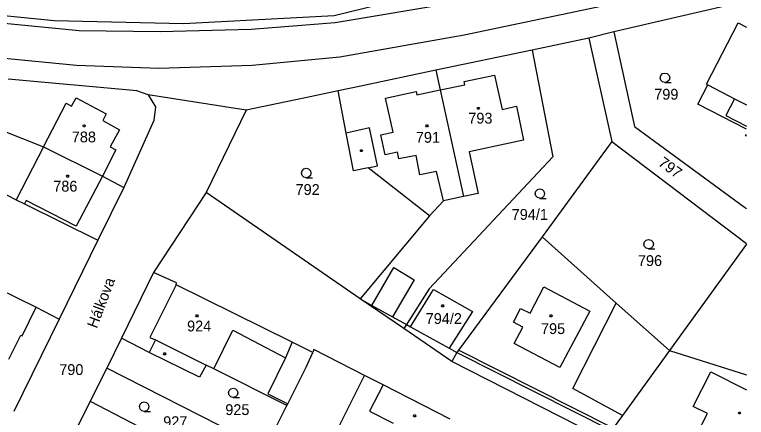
# Model space of a CAD drawing. Extents: x -621797 to -620972, y -1175539 to -1174697.
# Drawn here: x -621092 to -620977.2, y -1175193.8 to -1175130.5 of the extents above; entities that cross this region are included whole.
import ezdxf

# ---------------------------------------------------------------- set-up
doc = ezdxf.new("R2010")
doc.units = 0
for name, color, linetype in [('INZ mimo EON - nadz', 7, 'Continuous'), ('Rozvod plynu EON', 7, 'Continuous'), ('SDEL EON', 7, 'Continuous'), ('SDEL EON - popis', 7, 'Continuous'), ('Silnoproud EON', 7, 'Continuous'), ('Silnoproud EON - popis', 7, 'Continuous')]:
    doc.layers.add(name, color=color, linetype=linetype)

msp = doc.modelspace()

# ---------------------------------------------------------------- linework, layer by layer
at = {"layer": 'Rozvod plynu EON'}
for points in [[(-621019.15, -1175145.11), (-621019.06, -1175145.26), (-621019.15, -1175145.41), (-621019.33, -1175145.41), (-621019.42, -1175145.26), (-621019.33, -1175145.11)], [(-621081.02, -1175147.84), (-621080.93, -1175147.99), (-621081.02, -1175148.14), (-621081.2, -1175148.14), (-621081.29, -1175147.99), (-621081.2, -1175147.84)], [(-621027.19, -1175147.84), (-621027.1, -1175147.99), (-621027.19, -1175148.14), (-621027.37, -1175148.14), (-621027.46, -1175147.99), (-621027.37, -1175147.84)], [(-621037.49, -1175151.75), (-621037.4, -1175151.9), (-621037.49, -1175152.05), (-621037.67, -1175152.05), (-621037.76, -1175151.9), (-621037.67, -1175151.75)], [(-621083.61, -1175155.74), (-621083.52, -1175155.89), (-621083.61, -1175156.04), (-621083.79, -1175156.04), (-621083.88, -1175155.89), (-621083.79, -1175155.74)], [(-621024.75, -1175176.11), (-621024.66, -1175176.26), (-621024.75, -1175176.41), (-621024.93, -1175176.41), (-621025.02, -1175176.26), (-621024.93, -1175176.11)], [(-621063.3, -1175177.68), (-621063.21, -1175177.83), (-621063.3, -1175177.98), (-621063.48, -1175177.98), (-621063.57, -1175177.83), (-621063.48, -1175177.68)], [(-621007.71, -1175177.68), (-621007.62, -1175177.83), (-621007.71, -1175177.98), (-621007.89, -1175177.98), (-621007.98, -1175177.83), (-621007.89, -1175177.68)], [(-621068.39, -1175183.65), (-621068.3, -1175183.8), (-621068.39, -1175183.95), (-621068.57, -1175183.95), (-621068.66, -1175183.8), (-621068.57, -1175183.65)], [(-620978.14, -1175192.94), (-620978.05, -1175193.09), (-620978.14, -1175193.24), (-620978.32, -1175193.24), (-620978.41, -1175193.09), (-620978.32, -1175192.94)], [(-621029.15, -1175193.38), (-621029.06, -1175193.53), (-621029.15, -1175193.68), (-621029.33, -1175193.68), (-621029.42, -1175193.53), (-621029.33, -1175193.38)]]:
    msp.add_lwpolyline(points, close=True, dxfattribs=at)
at = {"layer": 'SDEL EON'}
for points in [[(-620989.92, -1175141.19), (-620990.3, -1175141.09), (-620990.57, -1175140.82), (-620990.67, -1175140.45), (-620990.57, -1175140.08), (-620990.3, -1175139.81), (-620989.93, -1175139.71), (-620989.56, -1175139.81), (-620989.29, -1175140.08), (-620989.19, -1175140.46), (-620989.29, -1175140.84), (-620989.56, -1175141.11), (-620989.94, -1175141.21), (-620988.94, -1175141.21)], [(-621046.23, -1175156.15), (-621046.61, -1175156.05), (-621046.88, -1175155.78), (-621046.98, -1175155.41), (-621046.88, -1175155.04), (-621046.61, -1175154.77), (-621046.24, -1175154.67), (-621045.87, -1175154.77), (-621045.6, -1175155.04), (-621045.5, -1175155.42), (-621045.6, -1175155.8), (-621045.87, -1175156.07), (-621046.25, -1175156.17), (-621045.25, -1175156.17)], [(-621009.55, -1175159.37), (-621009.93, -1175159.27), (-621010.2, -1175159), (-621010.3, -1175158.63), (-621010.2, -1175158.26), (-621009.93, -1175157.99), (-621009.56, -1175157.89), (-621009.19, -1175157.99), (-621008.92, -1175158.26), (-621008.82, -1175158.64), (-621008.92, -1175159.02), (-621009.19, -1175159.29), (-621009.57, -1175159.39), (-621008.57, -1175159.39)], [(-620992.48, -1175167.31), (-620992.86, -1175167.21), (-620993.13, -1175166.94), (-620993.23, -1175166.57), (-620993.13, -1175166.2), (-620992.86, -1175165.93), (-620992.49, -1175165.83), (-620992.12, -1175165.93), (-620991.85, -1175166.2), (-620991.75, -1175166.58), (-620991.85, -1175166.96), (-620992.12, -1175167.23), (-620992.5, -1175167.33), (-620991.5, -1175167.33)], [(-621057.7, -1175190.65), (-621058.08, -1175190.55), (-621058.35, -1175190.28), (-621058.45, -1175189.91), (-621058.35, -1175189.54), (-621058.08, -1175189.27), (-621057.71, -1175189.17), (-621057.34, -1175189.27), (-621057.07, -1175189.54), (-621056.97, -1175189.92), (-621057.07, -1175190.3), (-621057.34, -1175190.57), (-621057.72, -1175190.67), (-621056.72, -1175190.67)], [(-621071.69, -1175192.83), (-621072.07, -1175192.73), (-621072.34, -1175192.46), (-621072.44, -1175192.09), (-621072.34, -1175191.72), (-621072.07, -1175191.45), (-621071.7, -1175191.35), (-621071.33, -1175191.45), (-621071.06, -1175191.72), (-621070.96, -1175192.1), (-621071.06, -1175192.48), (-621071.33, -1175192.75), (-621071.71, -1175192.85), (-621070.71, -1175192.85)]]:
    msp.add_lwpolyline(points, dxfattribs=at)
at = {"layer": 'SDEL EON - popis'}
for p, q in [((-621197.6, -1175121.77), (-621081.88, -1175133.05)), ((-620977.15, -1175124.433), (-621021.43, -1175133.77)), ((-621082.31, -1175138.52), (-621199.05, -1175127.17)), ((-621041.68, -1175131.8), (-621022.28, -1175128.54)), ((-621054.9, -1175132.81), (-621041.68, -1175131.8)), ((-621081.88, -1175133.05), (-621069.17, -1175133.2)), ((-621069.17, -1175133.2), (-621054.9, -1175132.81)), ((-621021.43, -1175133.77), (-621040.97, -1175137.22)), ((-621040.97, -1175137.22), (-621054.75, -1175138.54)), ((-621069.38, -1175139.01), (-621082.31, -1175138.52)), ((-621054.75, -1175138.54), (-621069.38, -1175139.01)), ((-621021.47, -1175141.06), (-621016.68, -1175140.06)), ((-621016.68, -1175140.06), (-621015.5, -1175145.42)), ((-621021.37, -1175141.55), (-621021.47, -1175141.06)), ((-621028.88, -1175143.12), (-621025.24, -1175142.35)), ((-621025.24, -1175142.35), (-621021.37, -1175141.55)), ((-620983.21, -1175141.57), (-620979.02, -1175143.76)), ((-621083.09, -1175144.93), (-621082.36, -1175143.59)), ((-621082.36, -1175143.59), (-621077.64, -1175146.1)), ((-621033.8, -1175143.66), (-621028.98, -1175142.63)), ((-621032.61, -1175148.99), (-621033.8, -1175143.66)), ((-621028.98, -1175142.63), (-621028.88, -1175143.12)), ((-621087.48, -1175151.29), (-621083.96, -1175144.45)), ((-621083.96, -1175144.45), (-621083.09, -1175144.93)), ((-620979.02, -1175143.76), (-620980.36, -1175146.36)), ((-620979.02, -1175143.76), (-620977.15, -1175144.705)), ((-621015.5, -1175145.42), (-621013.72, -1175145.02)), ((-621013.72, -1175145.02), (-621013.23, -1175144.91)), ((-621013.23, -1175144.91), (-621012.12, -1175150.25)), ((-621077.64, -1175146.1), (-621078.19, -1175147.16)), ((-620980.36, -1175146.36), (-620977.15, -1175148.029)), ((-621078.19, -1175147.16), (-621075.58, -1175148.64)), ((-621075.58, -1175148.64), (-621077.03, -1175151.31)), ((-621036.29, -1175148.3), (-621039.97, -1175149.17)), ((-621035.04, -1175154.28), (-621036.29, -1175148.3)), ((-621034.55, -1175149.43), (-621032.61, -1175148.99)), ((-621033.88, -1175152.53), (-621034.55, -1175149.43)), ((-621012.12, -1175150.25), (-621014.32, -1175150.72)), ((-621087.48, -1175151.29), (-621091.76, -1175159.6)), ((-621077.03, -1175151.31), (-621076.12, -1175151.78)), ((-621014.32, -1175150.72), (-621020.65, -1175152.07)), ((-621076.12, -1175151.78), (-621078.21, -1175155.9)), ((-621031.92, -1175152.11), (-621033.88, -1175152.53)), ((-621031.69, -1175153.16), (-621031.92, -1175152.11)), ((-621029.01, -1175152.64), (-621031.69, -1175153.16)), ((-621028.39, -1175155.67), (-621029.01, -1175152.64)), ((-621020.65, -1175152.07), (-621019.23, -1175158.6)), ((-621036.5, -1175154.59), (-621035.04, -1175154.28)), ((-621078.21, -1175155.9), (-621082.34, -1175163.73)), ((-621025.8, -1175155.17), (-621028.39, -1175155.67)), ((-621024.71, -1175159.76), (-621025.8, -1175155.17)), ((-621019.23, -1175158.6), (-621021.55, -1175159.08)), ((-621090.19, -1175159.73), (-621090.46, -1175160.26)), ((-621082.34, -1175163.73), (-621090.19, -1175159.73)), ((-621035.93, -1175176.2), (-621032.49, -1175170.24)), ((-621032.49, -1175170.24), (-621029.29, -1175172.16)), ((-621029.29, -1175172.16), (-621032.72, -1175177.97)), ((-621066.67, -1175172.94), (-621070.8, -1175181.22)), ((-621011.11, -1175177.42), (-621008.94, -1175173.29)), ((-621008.94, -1175173.29), (-621001.73, -1175177.1)), ((-621037.76, -1175175.18), (-621035.93, -1175176.2)), ((-621004.38, -1175189.25), (-620997.6, -1175175.82)), ((-621090.86, -1175180.95), (-621088.62, -1175176.48)), ((-621035.93, -1175176.2), (-621032.72, -1175177.97)), ((-621013.72, -1175178.83), (-621012.59, -1175176.68)), ((-621012.59, -1175176.68), (-621011.11, -1175177.42)), ((-621032.72, -1175177.97), (-621030.53, -1175179.19)), ((-621001.73, -1175177.1), (-621006.41, -1175185.95)), ((-621012.26, -1175179.6), (-621013.72, -1175178.83)), ((-621060.74, -1175186.16), (-621057.77, -1175180.1)), ((-621057.77, -1175180.1), (-621049.52, -1175184.42)), ((-621029.87, -1175179.56), (-621023.8, -1175182.92)), ((-621013.62, -1175182.2), (-621012.26, -1175179.6)), ((-621092.93, -1175184.65), (-621091.04, -1175180.89)), ((-621091.04, -1175180.89), (-621090.86, -1175180.95)), ((-621070.8, -1175181.22), (-621069.93, -1175181.61)), ((-621069.93, -1175181.61), (-621070.89, -1175183.57)), ((-621069.93, -1175181.61), (-621061.96, -1175185.58)), ((-621048.48, -1175181.95), (-621049.52, -1175184.42)), ((-621006.41, -1175185.95), (-621013.62, -1175182.2)), ((-621022.58, -1175183.6), (-620998.3, -1175195.84)), ((-620998.04, -1175195.48), (-621022.32, -1175183.23)), ((-621049.52, -1175184.42), (-621052.29, -1175190.1)), ((-620985.52, -1175192.08), (-620982.72, -1175186.62)), ((-620982.72, -1175186.62), (-620977.15, -1175189.45)), ((-621034.16, -1175188.68), (-621036.29, -1175192.79)), ((-620996.61, -1175193.5), (-621004.38, -1175189.25)), ((-621052.29, -1175190.1), (-621049.16, -1175191.67)), ((-621036.29, -1175192.79), (-621032.61, -1175194.69)), ((-620983.25, -1175193.18), (-620985.52, -1175192.08)), ((-620985.07, -1175196.69), (-620983.25, -1175193.18))]:
    msp.add_line(p, q, dxfattribs=at)
at = {"layer": 'Silnoproud EON'}
for p, q in [((-621041.88, -1175130.69), (-620986.27, -1175116.91)), ((-621147.63, -1175125.29), (-621085.82, -1175131.48)), ((-620977.15, -1175128.429), (-620997.97, -1175133.24)), ((-621065.52, -1175131.94), (-621041.88, -1175130.69)), ((-621085.82, -1175131.48), (-621065.52, -1175131.94)), ((-620983.41, -1175141.47), (-620978.44, -1175131.83)), ((-620978.44, -1175131.83), (-620977.15, -1175132.494)), ((-620997.97, -1175133.24), (-621001.86, -1175134.24)), ((-620997.97, -1175133.24), (-620994.7, -1175148.1)), ((-621001.86, -1175134.24), (-621010.79, -1175136.1)), ((-621001.86, -1175134.24), (-620998.25, -1175150.46)), ((-621010.79, -1175136.1), (-621025.91, -1175139.25)), ((-621010.79, -1175136.1), (-621007.51, -1175152.89)), ((-621025.91, -1175139.25), (-621037.67, -1175141.77)), ((-621025.91, -1175139.25), (-621025.24, -1175142.35)), ((-621072.86, -1175142.5), (-621093.04, -1175140.67)), ((-621071.05, -1175143.14), (-621072.86, -1175142.5)), ((-621041.25, -1175142.53), (-621045.61, -1175143.46)), ((-621037.67, -1175141.77), (-621041.25, -1175142.53)), ((-621039.97, -1175149.17), (-621041.25, -1175142.53)), ((-621025.24, -1175142.35), (-621021.55, -1175159.08)), ((-620984.75, -1175144.58), (-620983.21, -1175141.57)), ((-620983.21, -1175141.57), (-620983.41, -1175141.47)), ((-621055.68, -1175145.55), (-621071.05, -1175143.14)), ((-621071.05, -1175143.14), (-621069.92, -1175145.02)), ((-621045.61, -1175143.46), (-621055.68, -1175145.55)), ((-620977.15, -1175148.538), (-620984.75, -1175144.58)), ((-621069.92, -1175145.02), (-621070.17, -1175147.15)), ((-621055.68, -1175145.55), (-621061.96, -1175158.46)), ((-621070.17, -1175147.15), (-621074.9, -1175157.7)), ((-620994.7, -1175148.1), (-620977.42, -1175160.79)), ((-621094.1, -1175148.7), (-621087.48, -1175151.29)), ((-621038.82, -1175155.08), (-621039.97, -1175149.17)), ((-620977.27, -1175149.58), (-620977.15, -1175149.348)), ((-620998.25, -1175150.46), (-621009.23, -1175165.42)), ((-620998.25, -1175150.46), (-620977.15, -1175166.482)), ((-620977.15, -1175149.643), (-620977.27, -1175149.58)), ((-621087.48, -1175151.29), (-621078.21, -1175155.9)), ((-621007.51, -1175152.89), (-621026.95, -1175173.59)), ((-621102.64, -1175154.09), (-621091.76, -1175159.6)), ((-621036.5, -1175154.59), (-621038.82, -1175155.08)), ((-621026.92, -1175162.12), (-621036.5, -1175154.59)), ((-621078.21, -1175155.9), (-621074.9, -1175157.7)), ((-621074.9, -1175157.7), (-621078.97, -1175165.95)), ((-621061.96, -1175158.46), (-621070.23, -1175171.01)), ((-621037.76, -1175175.18), (-621061.96, -1175158.46)), ((-621091.76, -1175159.6), (-621090.46, -1175160.26)), ((-621024.71, -1175159.76), (-621026.92, -1175162.12)), ((-621021.55, -1175159.08), (-621024.71, -1175159.76)), ((-621090.46, -1175160.26), (-621078.97, -1175165.95)), ((-620977.42, -1175160.79), (-620977.15, -1175160.987)), ((-621026.92, -1175162.12), (-621037.76, -1175175.18)), ((-621009.23, -1175165.42), (-621022.32, -1175183.23)), ((-621009.23, -1175165.42), (-620997.6, -1175175.82)), ((-621078.97, -1175165.95), (-621085.03, -1175178.33)), ((-620977.15, -1175166.589), (-620989.23, -1175183.29)), ((-621070.23, -1175171.01), (-621075.24, -1175181.32)), ((-621066.63, -1175172.66), (-621070.23, -1175171.01)), ((-621097.38, -1175172.19), (-621088.62, -1175176.48)), ((-621066.67, -1175172.94), (-621066.63, -1175172.66)), ((-621048.48, -1175181.95), (-621066.67, -1175172.94)), ((-621026.95, -1175173.59), (-621030.53, -1175179.19)), ((-621029.87, -1175179.56), (-621026.28, -1175173.7)), ((-621026.28, -1175173.7), (-621020.15, -1175177.15)), ((-621030.95, -1175179.84), (-621037.76, -1175175.18)), ((-620997.6, -1175175.82), (-620989.23, -1175183.29)), ((-621088.62, -1175176.48), (-621085.03, -1175178.33)), ((-621020.15, -1175177.15), (-621023.8, -1175182.92)), ((-621085.03, -1175178.33), (-621092.13, -1175192.87)), ((-621030.53, -1175179.19), (-621030.95, -1175179.84)), ((-621030.53, -1175179.19), (-621029.87, -1175179.56)), ((-621023.4, -1175185), (-621030.95, -1175179.84)), ((-621075.24, -1175181.32), (-621077.54, -1175186.04)), ((-621070.89, -1175183.57), (-621075.24, -1175181.32)), ((-621045.2, -1175183.58), (-621048.48, -1175181.95)), ((-621062.98, -1175187.47), (-621070.89, -1175183.57)), ((-621046.26, -1175185.87), (-621045.2, -1175183.58)), ((-621045.04, -1175183.14), (-621045.2, -1175183.58)), ((-621037.12, -1175187.18), (-621045.04, -1175183.14)), ((-621023.8, -1175182.92), (-621022.58, -1175183.6)), ((-621022.58, -1175183.6), (-621023.4, -1175185)), ((-621022.32, -1175183.23), (-621022.58, -1175183.6)), ((-620989.23, -1175183.29), (-620996.61, -1175193.5)), ((-620989.23, -1175183.29), (-620977.15, -1175187.103)), ((-620999.31, -1175197.24), (-621023.4, -1175185)), ((-621077.54, -1175186.04), (-621080.15, -1175191.22)), ((-621052.68, -1175198.68), (-621077.54, -1175186.04)), ((-621061.96, -1175185.58), (-621062.98, -1175187.47)), ((-621060.74, -1175186.16), (-621061.96, -1175185.58)), ((-621049.27, -1175191.89), (-621060.74, -1175186.16)), ((-621049.16, -1175191.67), (-621046.26, -1175185.87)), ((-621042.54, -1175198.11), (-621037.12, -1175187.18)), ((-621034.16, -1175188.68), (-621037.12, -1175187.18)), ((-621023.64, -1175194.04), (-621034.16, -1175188.68)), ((-621080.15, -1175191.22), (-621085.32, -1175201.53)), ((-621080.15, -1175191.22), (-621063.33, -1175199.97)), ((-621052.68, -1175198.68), (-621049.27, -1175191.89)), ((-621049.27, -1175191.89), (-621049.16, -1175191.67)), ((-620996.61, -1175193.5), (-620998.04, -1175195.48))]:
    msp.add_line(p, q, dxfattribs=at)

# ---------------------------------------------------------------- texts
at = {"layer": 'INZ mimo EON - nadz'}
msp.add_text('Hálkova', height=1.7, rotation=69.32789, dxfattribs=at).set_placement((-621079.124, -1175179.906))
at = {"layer": 'Silnoproud EON - popis'}
for s, p in [('799', (-620991.613, -1175143.89)), ('793', (-621020.803, -1175147.65)), ('788', (-621083.053, -1175150.6)), ('791', (-621029.043, -1175150.66)), ('786', (-621085.963, -1175158.33)), ('792', (-621047.923, -1175158.85)), ('794/1', (-621013.993, -1175162.76)), ('796', (-620994.173, -1175170.01)), ('794/2', (-621027.493, -1175179.11)), ('924', (-621064.953, -1175180.28)), ('795', (-621009.393, -1175180.69)), ('790', (-621085.023, -1175187.12)), ('925', (-621058.953, -1175193.41)), ('927', (-621068.703, -1175195.3))]:
    msp.add_text(s, height=1.7, dxfattribs=at).set_placement(p)
msp.add_text('797', height=1.7, rotation=324.00763, dxfattribs=at).set_placement((-620991.118, -1175154.11))

doc.saveas('drawing.dxf')
